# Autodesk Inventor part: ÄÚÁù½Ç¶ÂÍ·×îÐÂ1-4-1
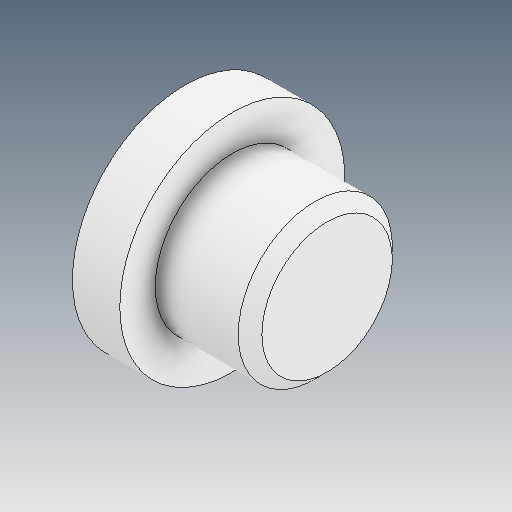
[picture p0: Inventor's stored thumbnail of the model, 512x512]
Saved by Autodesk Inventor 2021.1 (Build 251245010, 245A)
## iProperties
Created: 2021-05
Part Number: ÄÚÁù½Ç¶ÂÍ·×îÐÂ1-4-1
Material: Ogólny
Document SubType Name: Modeling
Designer: user
Density: 1 g/cm^3
Appearance: Domyślna
Author: user
Revision Number: ÈÎºÎ
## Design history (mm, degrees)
feature "ÊäÈë1"
node "Bryła1"
